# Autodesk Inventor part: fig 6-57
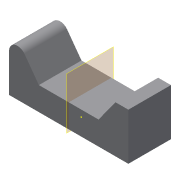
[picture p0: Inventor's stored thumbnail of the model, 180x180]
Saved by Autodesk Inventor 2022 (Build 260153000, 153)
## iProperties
Created: 2011-07
Part Number: fig 6-57
Material: Generic
Document SubType Name: Modeling
Designer: CadCim
Density: 1 g/cm^3
Appearance: Default
Author: CadCim
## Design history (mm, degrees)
sketch "Sketch1"
  geometry: 1 further point
sketch "Sketch2"
  geometry: L1 (3, -4)-(17, -4); L2 (17, -4)-(17, 7); L3 (17, 7)-(14, 7); L4 (14, 7)-(10, 1.5); L5 (10, 1.5)-(3, 1.5); L6 (3, -4)-(-11, -4); L7 (-11, -4)-(-11, 7); L8 (-11, 7)-(-8, 7); L9 (-8, 7)-(-4, 1.5); L10 (-4, 1.5)-(3, 1.5); 1 further point
  constraints: 20 end point, 2 parallel, 1 perpendicular
extrude "Extrusion1" new body sketch "Sketch2" distance "d0" = 10; taper "d1" = 0 deg
fillet "Fillet1" dims "d2" = 2
workplane "Work Plane1"
body "Solid1"
